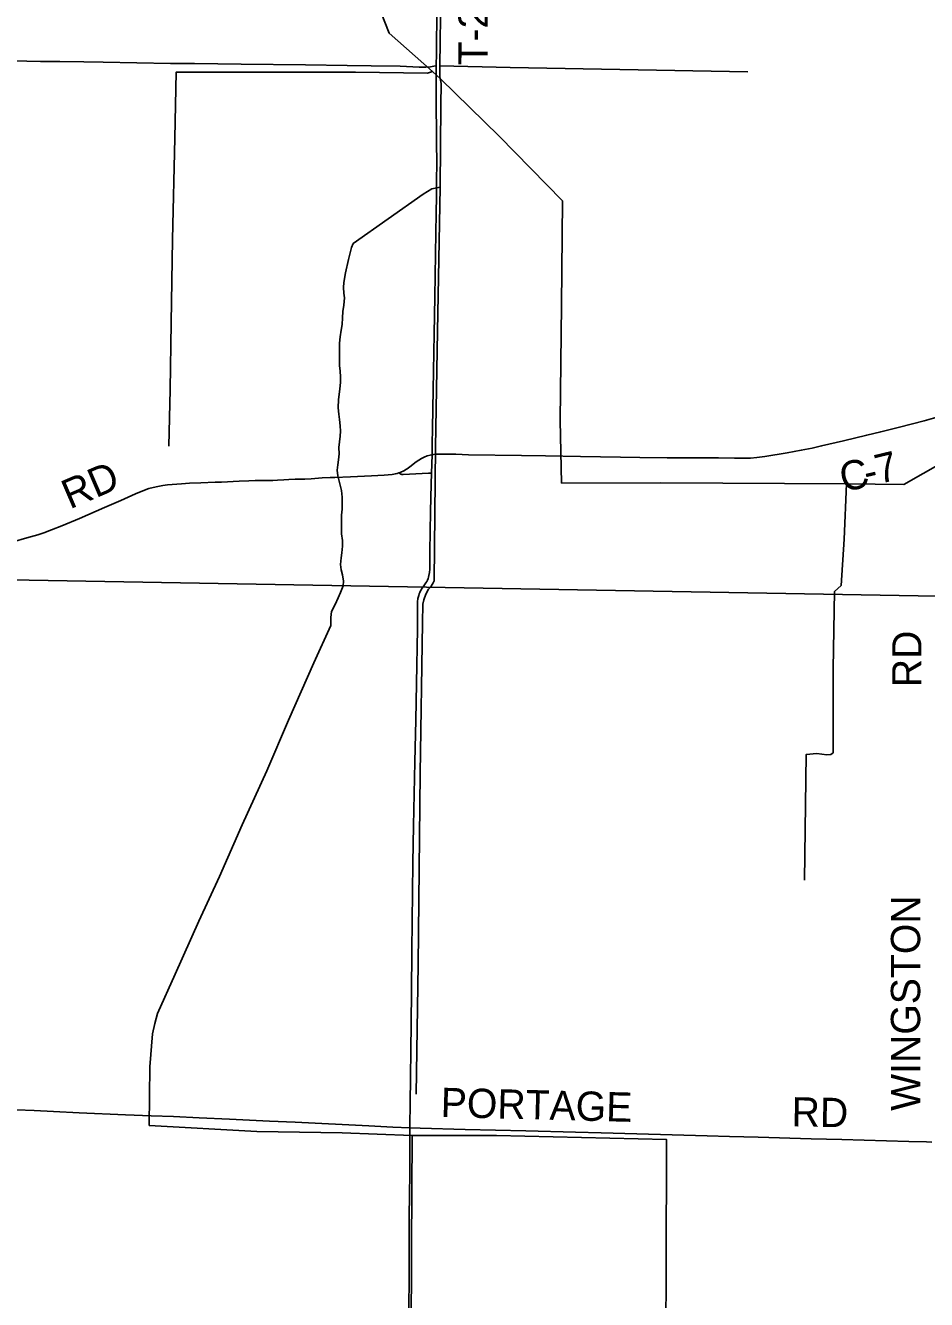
# Model space of a CAD drawing. Extents: x 0 to 680, y 0 to 834.
# Drawn here: x 120.8 to 187.9, y 223.2 to 318.1 of the extents above; entities that cross this region are included whole.
import ezdxf

# ---------------------------------------------------------------- set-up
doc = ezdxf.new("R2010")
doc.units = 0
for name, color, linetype in [('GM_X_County_Road', 7, 'Continuous'), ('GM_X_County_Road_Text', 7, 'Continuous'), ('GM_X_Minor_River', 7, 'Continuous'), ('GM_X_Township_Road', 7, 'Continuous'), ('GM_X_Township_Road_Text', 7, 'Continuous')]:
    doc.layers.add(name, color=color, linetype=linetype)

msp = doc.modelspace()

# ---------------------------------------------------------------- linework, layer by layer
at = {"layer": 'GM_X_County_Road'}
for points in [[(151.119, 286.139), (151.213, 286.156), (151.447, 286.177), (151.803, 286.181), (152.876, 286.176), (153.826, 286.143), (157.759, 286.075), (159.548, 286.048), (162.169, 286.014), (165.153, 285.958), (166.585, 285.939), (168.615, 285.923), (170.525, 285.905), (172.435, 285.906), (173.629, 285.886), (174.346, 285.88), (174.825, 285.895), (175.301, 285.937), (175.895, 286.013), (177.546, 286.277), (178.603, 286.474), (179.42, 286.643), (180.117, 286.797), (181.743, 287.181), (183.476, 287.607), (184.518, 287.858), (185.909, 288.193), (187.761, 288.664), (188.797, 288.956)], [(148.629, 284.787), (148.737, 284.825), (148.836, 284.867), (148.956, 284.925), (149.052, 284.976), (149.168, 285.043), (149.259, 285.1), (149.457, 285.237), (149.928, 285.605), (150.121, 285.741), (150.323, 285.862), (150.535, 285.966), (150.754, 286.05), (150.981, 286.114), (151.119, 286.139)], [(119.91, 279.667), (120.946, 279.949), (121.75, 280.183), (122.205, 280.331), (122.764, 280.54), (123.541, 280.85), (124.863, 281.403), (126.724, 282.214), (127.926, 282.745), (129.019, 283.223), (129.57, 283.451), (130.014, 283.617), (130.355, 283.714), (130.703, 283.787), (131.055, 283.845), (131.409, 283.89), (131.764, 283.923), (132.115, 283.956), (132.464, 283.986), (133.052, 284.021), (133.886, 284.048), (134.961, 284.087), (135.438, 284.106), (136.748, 284.17), (137.461, 284.204), (137.938, 284.215), (138.773, 284.213), (139.251, 284.219), (139.61, 284.24), (140.085, 284.278), (140.441, 284.295), (140.917, 284.316), (141.63, 284.331), (142.106, 284.359), (142.935, 284.41), (143.521, 284.439), (143.872, 284.453), (145.048, 284.5), (146.59, 284.565), (147.542, 284.621), (148.138, 284.676), (148.263, 284.695), (148.376, 284.717), (148.501, 284.746), (148.629, 284.787)], [(148.629, 284.787), (148.723, 284.734), (148.785, 284.699), (148.817, 284.687), (148.861, 284.677), (148.906, 284.672), (148.953, 284.67), (149.428, 284.69), (150.852, 284.762), (151.075, 284.774)]]:
    msp.add_lwpolyline(points, dxfattribs=at)
at = {"layer": 'GM_X_Minor_River'}
for points in [[(145.503, 323.259), (145.806, 322.918), (147.918, 317.543), (151.144, 314.689), (151.739, 314.148), (156.098, 309.861), (160.819, 305.062), (160.752, 297.286), (160.639, 288.68), (160.756, 284.025), (168.143, 284.048), (181.969, 283.965), (186.238, 283.923), (189.113, 285.564)], [(149.925, 238.528), (150.071, 248.17), (150.23, 262.392), (150.395, 273.61), (150.413, 275.01), (150.502, 275.345), (150.649, 275.754), (150.854, 276.118), (151.044, 276.35), (151.205, 276.598), (151.264, 276.758), (151.366, 286.707), (151.508, 295.314), (151.715, 306.08), (151.763, 312.178), (151.797, 313.783), (151.681, 314.279), (151.682, 314.527), (151.699, 315.111), (151.773, 320.538)], [(151.699, 315.111), (156.929, 314.994), (174.616, 314.651)], [(145.417, 314.633), (136.823, 314.645), (132.063, 314.637), (131.967, 309.727), (131.783, 302.182), (131.694, 295.975), (131.611, 290.993), (131.512, 286.783)], [(151.144, 314.689), (150.764, 314.559), (145.417, 314.633)], [(151.715, 306.08), (151.088, 305.951), (150.461, 305.544), (145.248, 301.868)], [(143.585, 273.428), (143.577, 274.008), (143.614, 274.473), (143.884, 274.979), (144.126, 275.485), (144.293, 275.89), (144.504, 276.367), (144.525, 276.731), (144.431, 277.185), (144.35, 277.579), (144.298, 277.974), (144.335, 278.454), (144.4, 278.846), (144.452, 279.341), (144.43, 279.749), (144.365, 280.246), (144.374, 280.785), (144.367, 281.222), (144.374, 281.63), (144.41, 282.081), (144.425, 282.984), (144.361, 283.481), (144.238, 283.978), (144.102, 284.578), (144.051, 285.002), (144.086, 285.38), (144.151, 285.772), (144.188, 286.209), (144.181, 286.675), (144.217, 287.112), (144.268, 287.533), (144.289, 287.897), (144.266, 288.306), (144.215, 288.758), (144.164, 289.167), (144.128, 289.634), (144.138, 290.246), (144.189, 290.639), (144.239, 291.06), (144.291, 291.526), (144.297, 291.919), (144.262, 292.401), (144.224, 292.766), (144.217, 293.218), (144.21, 293.684), (144.223, 294.456), (144.274, 294.922), (144.341, 295.43), (144.406, 295.852), (144.443, 296.332), (144.466, 296.798), (144.532, 297.278), (144.585, 297.816), (144.547, 298.181), (144.525, 298.59), (144.545, 298.968), (144.677, 299.689), (144.887, 300.685), (145.119, 301.582), (145.248, 301.868)], [(181.969, 283.965), (181.797, 279.866), (181.568, 276.409), (181.071, 275.944), (180.967, 270.211), (180.978, 264.419), (180.977, 263.952), (180.802, 263.822), (180.496, 263.779), (179.768, 263.898), (178.966, 263.812), (178.85, 254.462)], [(143.585, 273.428), (142.312, 270.633), (140.421, 266.38), (138.814, 262.604), (136.97, 258.584), (135.289, 254.736), (133.734, 251.41), (131.979, 247.462), (130.677, 244.526), (130.461, 243.772), (130.288, 243.017), (130.087, 240.558), (130.058, 236.187), (138.075, 235.748), (144.423, 235.642)], [(144.423, 235.642), (149.639, 235.452), (155.904, 235.433), (168.578, 235.134), (168.549, 225.435), (168.49, 215.999), (173.428, 215.751), (187.706, 215.418)], [(149.639, 235.452), (149.57, 227.153), (149.526, 213.123), (149.417, 196.921), (149.441, 195.477)]]:
    msp.add_lwpolyline(points, dxfattribs=at)
at = {"layer": 'GM_X_Township_Road'}
msp.add_line((151.075, 284.774), (151.119, 286.139), dxfattribs=at)
for points in [[(151.428, 315.098), (151.442, 316.043), (151.463, 319.385), (151.48, 320.817), (151.476, 321.245)], [(111.825, 315.686), (112.46, 315.616), (113.358, 315.599), (115.031, 315.56), (117.54, 315.521), (119.93, 315.485), (121.961, 315.436), (123.395, 315.424), (125.187, 315.395), (126.621, 315.375), (131.639, 315.29), (133.432, 315.282), (136.897, 315.232), (141.677, 315.169), (144.784, 315.132), (146.576, 315.1), (148.727, 315.083), (150.16, 315.012), (150.637, 315.013), (150.995, 315.037), (151.232, 315.071), (151.428, 315.098)], [(151.119, 286.139), (151.118, 286.564), (151.117, 286.922), (151.15, 288.115), (151.196, 290.979), (151.263, 295.157), (151.312, 297.902), (151.398, 302.675), (151.417, 304.108), (151.436, 305.42), (151.443, 306.614), (151.458, 307.807), (151.447, 309.478), (151.427, 312.82), (151.421, 314.611), (151.428, 315.098)], [(150.849, 277.025), (150.88, 277.141), (150.919, 277.376), (150.936, 277.614), (150.952, 278.927), (151.003, 281.91), (151.049, 283.939), (151.075, 284.774)], [(111.242, 276.965), (228.132, 274.916), (231.712, 274.79), (234.217, 274.711), (236.245, 274.646), (239.705, 274.555), (244.836, 274.407), (247.699, 274.316), (249.369, 274.266), (253.425, 274.135), (255.215, 274.078), (257.83, 273.986), (260.573, 273.913), (263.437, 273.841), (265.584, 273.782), (266.506, 273.748)], [(149.454, 236.017), (149.45, 236.296), (149.477, 237.728), (149.514, 239.876), (149.523, 241.666), (149.575, 246.081), (149.606, 249.184), (149.676, 255.748), (149.728, 258.493), (149.788, 260.879), (149.829, 263.265), (149.904, 266.367), (149.962, 269.112), (150.02, 273.169), (150.015, 274.84), (150.031, 275.198), (150.064, 275.434), (150.121, 275.665), (150.16, 275.778), (150.206, 275.888), (150.259, 275.995), (150.381, 276.2), (150.51, 276.385)], [(150.51, 276.385), (150.654, 276.592), (150.714, 276.695), (150.767, 276.802), (150.812, 276.912), (150.849, 277.025)], [(111.072, 237.987), (111.361, 237.943), (111.831, 237.87), (112.66, 237.756), (113.373, 237.678), (114.089, 237.623), (116.951, 237.482), (120.172, 237.36), (121.483, 237.296), (122.915, 237.237), (124.822, 237.139), (128.281, 236.978), (130.19, 236.915), (131.86, 236.848), (133.768, 236.757), (136.034, 236.661), (139.015, 236.514), (140.923, 236.425), (146.409, 236.165), (148.197, 236.071), (149.454, 236.017)], [(149.2, 197.36), (149.199, 198.465), (149.227, 200.613), (149.26, 205.864), (149.285, 208.132), (149.328, 213.86), (149.328, 215.65), (149.34, 216.724), (149.39, 222.214), (149.403, 225.197), (149.409, 227.704), (149.417, 229.494), (149.433, 230.926), (149.45, 232.716), (149.464, 235.342), (149.454, 236.017)], [(149.454, 236.017), (150.225, 235.985), (153.566, 235.88), (158.102, 235.782), (161.801, 235.683), (163.711, 235.635), (168.126, 235.52), (171.587, 235.415), (173.258, 235.368), (175.406, 235.307), (179.344, 235.202), (181.612, 235.151), (186.624, 235.004), (187.936, 234.959), (188.313, 234.946)]]:
    msp.add_lwpolyline(points, dxfattribs=at)

# ---------------------------------------------------------------- texts
at = {"layer": 'GM_X_County_Road_Text'}
for s, height, rotation, p in [('C', 2.182, 12.96653, (181.743, 283.342)), ('7', 2.182, 13.59494, (184.388, 283.953)), ('RD', 2.1818, 23.26413, (124.138, 282.064)), ('-', 2.182, 13.05976, (183.493, 283.745))]:
    msp.add_text(s, height=height, rotation=rotation, dxfattribs=at).set_placement(p)
at = {"layer": 'GM_X_Township_Road_Text'}
for s, rotation, p in [('T-29', 89.66187, (155.24, 315.129)), ('RD', 90, (187.555, 268.828)), ('WINGSTON', 90, (187.458, 237.276)), ('PORTAGE', 358.51788, (151.735, 236.821)), ('RD', 359.01279, (177.868, 236.118))]:
    msp.add_text(s, height=2.1818, rotation=rotation, dxfattribs=at).set_placement(p)

doc.saveas('drawing.dxf')
